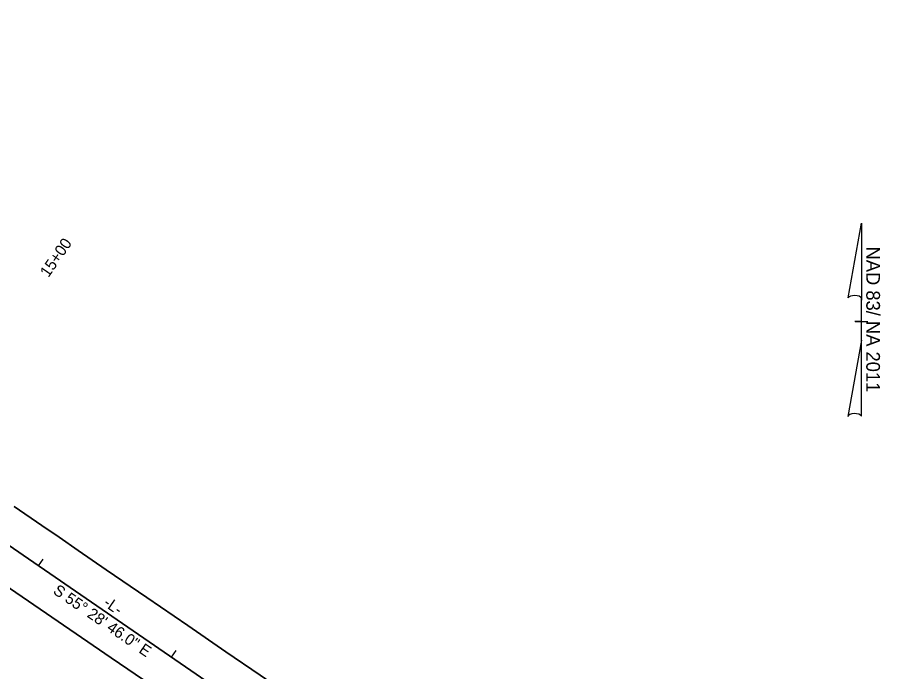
# Model space of a CAD drawing. Extents: x 1616561 to 1622460, y 896726 to 899651.
# Drawn here: x 1618541 to 1619076, y 898710 to 899116 of the extents above; entities that cross this region are included whole.
import ezdxf

# ---------------------------------------------------------------- set-up
doc = ezdxf.new("R2010")
doc.units = 0
for name, color, linetype in [('Prop Dimension', 7, 'Continuous'), ('Prop North Arrow NAD83 for Plan Sheets CELL', 7, 'Continuous'), ('Prop Shade Light', 7, 'Continuous'), ('Prop Superelevation  Arrow CELL', 7, 'Continuous'), ('Prop Terminator CELL', 7, 'Continuous'), ('Scratch_Level_1', 7, 'Continuous'), ('Sheet Cutting Line CELL', 7, 'Continuous')]:
    doc.layers.add(name, color=color, linetype=linetype)

msp = doc.modelspace()

# ---------------------------------------------------------------- linework, layer by layer
at = {"layer": 'Prop North Arrow NAD83 for Plan Sheets CELL'}
for p, q in [((1619055.99, 898941.78), (1619064.21, 898988.13)), ((1619064.26, 898988.13), (1619064.21, 898988.13)), ((1619064.26, 898988.13), (1619064.21, 898988.13)), ((1619064.26, 898988.13), (1619064.24, 898940.33)), ((1619064.23, 898915.53), (1619064.24, 898941.73)), ((1619064.24, 898940.33), (1619064.24, 898941.68)), ((1619060.24, 898927.13), (1619060.19, 898927.13)), ((1619063.79, 898927.13), (1619060.24, 898927.13)), ((1619060.29, 898927.13), (1619068.29, 898927.12)), ((1619064.23, 898915.53), (1619055.87, 898868.28)), ((1619064.27, 898868.48), (1619064.23, 898915.53))]:
    msp.add_line(p, q, dxfattribs=at)
for centre, start_param, end_param in [((1619060.13, 898941.28), 0.216388, 2.908219), ((1619060.1, 898868.11), 0.201328, 3.141593)]:
    msp.add_ellipse(centre, major_axis=(4.23, -0.03), ratio=0.461098, start_param=start_param, end_param=end_param, dxfattribs=at)
at = {"layer": 'Prop Shade Light'}
for p, q in [((1618059.8, 899115.77), (1618801.33, 898605.73)), ((1618801.33, 898605.73), (1618059.8, 899115.77))]:
    msp.add_line(p, q, dxfattribs=at)
for points in [[(1618773.4, 898651.52), (1618750.87, 898667.1), (1618726.65, 898683.63), (1618702.01, 898700.61), (1618691.56, 898707.86), (1618670.18, 898722.47), (1618646.62, 898738.71), (1618621.31, 898755.98), (1618596.1, 898773.27), (1618578.76, 898785.19), (1618566.83, 898793.5), (1618556.18, 898800.72), (1618539.02, 898812.52)], [(1618532.75, 898764.19), (1618555.15, 898748.82), (1618573.55, 898736.29), (1618599.06, 898718.7), (1618624.26, 898701.44), (1618647.12, 898685.72), (1618658.86, 898677.65), (1618669.7, 898670.24), (1618679.04, 898663.8), (1618703.51, 898646.86), (1618726.83, 898630.68), (1618748.38, 898616.08), (1618748.82, 898615.74)]]:
    msp.add_lwpolyline(points, dxfattribs=at)
at = {"layer": 'Prop Superelevation  Arrow CELL'}
for p, q in [((1618554.15, 898775.74), (1618556.99, 898779.86)), ((1618636.54, 898719.07), (1618639.38, 898723.19))]:
    msp.add_line(p, q, dxfattribs=at)
at = {"layer": 'Prop Terminator CELL'}
for points in [[(1618539.02, 898812.52), (1618556.18, 898800.72), (1618566.83, 898793.5), (1618578.76, 898785.19), (1618596.1, 898773.27), (1618621.31, 898755.98), (1618646.62, 898738.71), (1618670.18, 898722.47), (1618691.56, 898707.86), (1618702.01, 898700.61), (1618726.65, 898683.63), (1618750.87, 898667.1), (1618773.4, 898651.52)], [(1618748.38, 898616.08), (1618726.83, 898630.68), (1618703.51, 898646.86), (1618679.04, 898663.8), (1618669.7, 898670.24), (1618658.86, 898677.65), (1618647.12, 898685.72), (1618624.26, 898701.44), (1618599.06, 898718.7), (1618573.55, 898736.29), (1618555.15, 898748.82), (1618532.75, 898764.19)]]:
    msp.add_lwpolyline(points, dxfattribs=at)
at = {"layer": 'Sheet Cutting Line CELL'}
msp.add_line((1618059.8, 899115.77), (1618804.04, 898603.87), dxfattribs=at)

# ---------------------------------------------------------------- texts
at = {"layer": 'Prop Dimension'}
msp.add_text('15+00', height=7, rotation=55.4794, dxfattribs=at).set_placement((1618560.25, 898954.05))
at = {"layer": 'Prop North Arrow NAD83 for Plan Sheets CELL'}
msp.add_text('NAD 83/ NA 2011', height=8.5, rotation=269.9808, dxfattribs=at).set_placement((1619067.25, 898973.62))
at = {"layer": 'Scratch_Level_1'}
for s, p in [('S 55%%d 28\' 46.0" E', (1618562.58, 898758.91)), ('-L-', (1618593.8, 898751.36))]:
    msp.add_text(s, height=7, rotation=325.4794, dxfattribs=at).set_placement(p)

doc.saveas('drawing.dxf')
